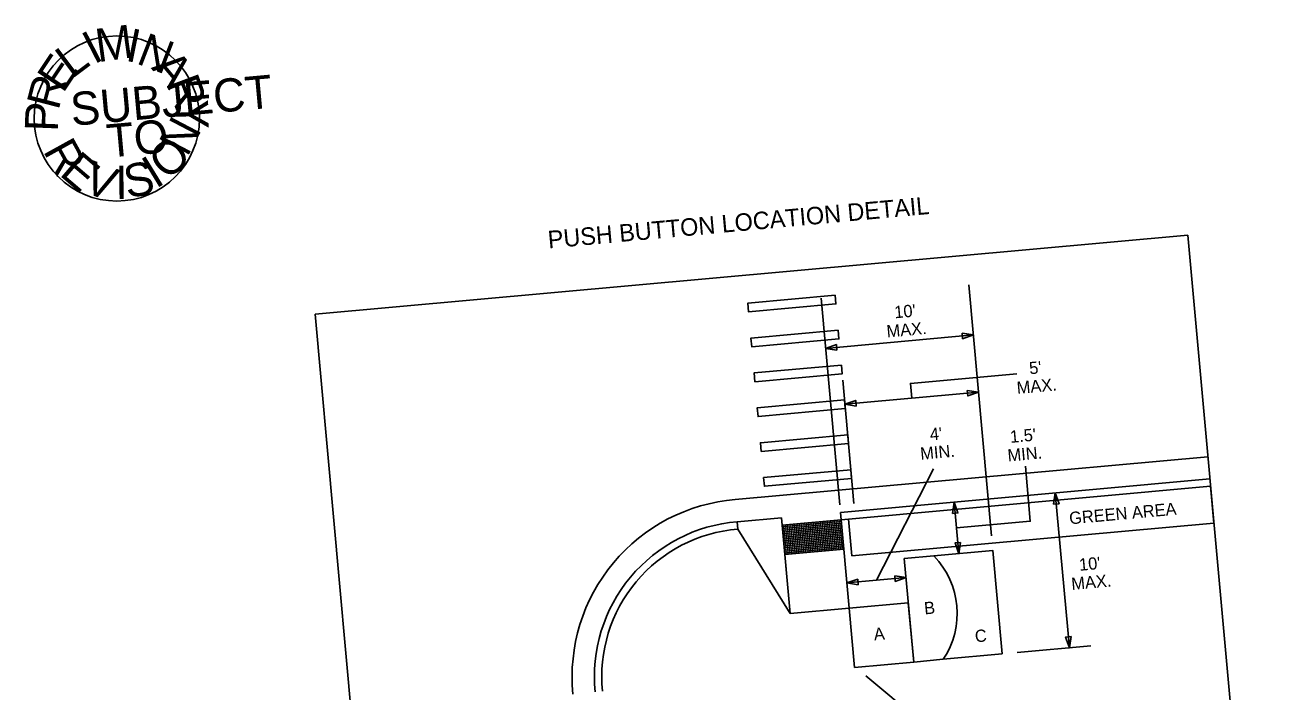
# Model space of a CAD drawing. Extents: x 1277218 to 1279252, y 196905 to 197529.
# Drawn here: x 1278236.5 to 1278669.3, y 197213 to 197445.9 of the extents above; entities that cross this region are included whole.
import ezdxf

# ---------------------------------------------------------------- set-up
doc = ezdxf.new("R2010")
doc.units = 0
doc.layers.add('C-ANNO-SYMB', color=7, linetype='Continuous')
doc.layers.add('C-TOPO-SURF-VOID', color=7, linetype='Continuous')

msp = doc.modelspace()

# ---------------------------------------------------------------- linework, layer by layer
at = {"layer": 'C-ANNO-SYMB'}
msp.add_circle((1278268.61, 197413.17), 28.85, dxfattribs=at)
at = {"layer": 'C-TOPO-SURF-VOID'}
for p, q in [((1278337.83, 197344.75), (1278642.58, 197372.36)), ((1278642.58, 197372.36), (1278669.26, 197077.94)), ((1278574.07, 197267.33), (1278566.13, 197355.03)), ((1278521.08, 197278.13), (1278514.54, 197350.36)), ((1278364.51, 197050.32), (1278337.83, 197344.75)), ((1278516.12, 197332.85), (1278567.71, 197337.52)), ((1278526, 197278.58), (1278522.09, 197321.73)), ((1278522.85, 197313.31), (1278569.52, 197317.54)), ((1278484.5, 197280.02), (1278649.59, 197294.98)), ((1278533.87, 197251.81), (1278553.76, 197290.79)), ((1278521.31, 197275.55), (1278650.29, 197287.24)), ((1278521.55, 197272.97), (1278650.52, 197284.66)), ((1278651.69, 197271.76), (1278650.52, 197284.66)), ((1278596.32, 197282.35), (1278601.23, 197228.18)), ((1278524.35, 197242.02), (1278521.31, 197275.55)), ((1278560.98, 197279.15), (1278562.61, 197261.09)), ((1278485.2, 197272.28), (1278500.68, 197273.68)), ((1278485.2, 197272.28), (1278485.44, 197269.7)), ((1278503.72, 197240.15), (1278500.68, 197273.68)), ((1278521.55, 197272.97), (1278500.91, 197271.1)), ((1278525.3, 197260.31), (1278524.13, 197273.21)), ((1278525.3, 197260.31), (1278651.69, 197271.76)), ((1278485.44, 197269.7), (1278503.72, 197240.15)), ((1278500.91, 197271.1), (1278503.72, 197240.15)), ((1278522.48, 197262.66), (1278501.85, 197260.79)), ((1278543.59, 197259.37), (1278553.9, 197260.3)), ((1278546.86, 197223.25), (1278543.59, 197259.37)), ((1278523.55, 197250.87), (1278544.19, 197252.74)), ((1278503.72, 197240.15), (1278524.35, 197242.02)), ((1278582.97, 197226.53), (1278608.77, 197228.86)), ((1278546.86, 197223.25), (1278557.18, 197224.19)), ((1278557.18, 197224.19), (1278577.81, 197226.06)), ((1278530.19, 197218.42), (1278550.08, 197201.84))]:
    msp.add_line(p, q, dxfattribs=at)
for points in [[(1278519.4, 197351.4), (1278519.68, 197348.36), (1278489.2, 197345.59), (1278488.93, 197348.64)], [(1278520.51, 197339.21), (1278520.78, 197336.17), (1278490.31, 197333.4), (1278490.03, 197336.45)], [(1278563.76, 197338.14), (1278567.71, 197337.52), (1278563.93, 197336.21)], [(1278520.08, 197332.23), (1278516.12, 197332.85), (1278519.9, 197334.17)], [(1278521.61, 197327.02), (1278521.89, 197323.98), (1278491.41, 197321.21), (1278491.14, 197324.26)], [(1278522.71, 197314.83), (1278522.99, 197311.79), (1278492.52, 197309.02), (1278492.24, 197312.07)], [(1278526.81, 197312.69), (1278522.85, 197313.31), (1278526.63, 197314.63)], [(1278565.57, 197318.16), (1278569.52, 197317.54), (1278565.74, 197316.22)], [(1278523.82, 197302.64), (1278524.1, 197299.6), (1278493.62, 197296.84), (1278493.34, 197299.88)], [(1278524.92, 197290.45), (1278525.2, 197287.41), (1278494.73, 197284.65), (1278494.45, 197287.69)], [(1278595.7, 197278.39), (1278596.32, 197282.35), (1278597.64, 197278.57)], [(1278560.36, 197275.19), (1278560.98, 197279.15), (1278562.29, 197275.37)], [(1278563.23, 197265.05), (1278562.61, 197261.09), (1278561.3, 197264.87)], [(1278527.51, 197250.25), (1278523.55, 197250.87), (1278527.33, 197252.19)], [(1278540.23, 197253.36), (1278544.19, 197252.74), (1278540.41, 197251.42)], [(1278524.35, 197242.02), (1278526.22, 197221.38), (1278546.86, 197223.25), (1278544.99, 197243.89)], [(1278601.84, 197232.14), (1278601.23, 197228.18), (1278599.91, 197231.96)]]:
    msp.add_lwpolyline(points, close=True, dxfattribs=at)
for points in [[(1278546.19, 197315.42), (1278545.72, 197320.58), (1278582.84, 197323.95)], [(1278561.8, 197270.12), (1278587.59, 197272.46), (1278585.85, 197291.66)], [(1278577.81, 197226.06), (1278574.54, 197262.17), (1278553.9, 197260.3)]]:
    msp.add_lwpolyline(points, dxfattribs=at)
for centre in [(1278507.02, 197271.04), (1278507.63, 197271.1), (1278508.24, 197271.15), (1278508.85, 197271.21), (1278509.46, 197271.26), (1278510.07, 197271.32), (1278510.68, 197271.37), (1278511.29, 197271.43), (1278511.9, 197271.49), (1278512.5, 197271.54), (1278513.11, 197271.6), (1278513.72, 197271.65), (1278513.78, 197271.04), (1278514.33, 197271.71), (1278514.39, 197271.1), (1278514.94, 197271.76), (1278515, 197271.15), (1278515.55, 197271.82), (1278515.61, 197271.21), (1278516.16, 197271.87), (1278516.22, 197271.26), (1278516.77, 197271.93), (1278516.83, 197271.32), (1278517.38, 197271.98), (1278517.44, 197271.37), (1278517.99, 197272.04), (1278518.05, 197271.43), (1278518.6, 197272.09), (1278518.65, 197271.48), (1278519.21, 197272.15), (1278519.26, 197271.54), (1278519.82, 197272.2), (1278519.87, 197271.59), (1278520.43, 197272.26), (1278520.48, 197271.65), (1278520.54, 197271.04), (1278521.04, 197272.31), (1278521.09, 197271.7), (1278521.15, 197271.09), (1278501.53, 197270.55), (1278501.59, 197269.94), (1278501.64, 197269.33), (1278501.7, 197268.72), (1278501.75, 197268.11), (1278501.81, 197267.5), (1278501.87, 197266.89), (1278502.14, 197270.6), (1278502.2, 197269.99), (1278502.25, 197269.38), (1278502.31, 197268.77), (1278502.36, 197268.16), (1278502.42, 197267.55), (1278502.47, 197266.94), (1278502.75, 197270.66), (1278502.81, 197270.05), (1278502.86, 197269.44), (1278502.92, 197268.83), (1278502.97, 197268.22), (1278503.03, 197267.61), (1278503.08, 197267), (1278503.36, 197270.71), (1278503.42, 197270.1), (1278503.47, 197269.49), (1278503.53, 197268.88), (1278503.58, 197268.27), (1278503.64, 197267.66), (1278503.69, 197267.05), (1278503.97, 197270.77), (1278504.03, 197270.16), (1278504.08, 197269.55), (1278504.14, 197268.94), (1278504.19, 197268.33), (1278504.25, 197267.72), (1278504.3, 197267.11), (1278504.58, 197270.82), (1278504.64, 197270.21), (1278504.69, 197269.6), (1278504.75, 197268.99), (1278504.8, 197268.38), (1278504.86, 197267.77), (1278504.91, 197267.17), (1278505.19, 197270.88), (1278505.25, 197270.27), (1278505.3, 197269.66), (1278505.36, 197269.05), (1278505.41, 197268.44), (1278505.47, 197267.83), (1278505.52, 197267.22), (1278505.8, 197270.93), (1278505.86, 197270.32), (1278505.91, 197269.71), (1278505.97, 197269.1), (1278506.02, 197268.49), (1278506.08, 197267.89), (1278506.13, 197267.28), (1278506.41, 197270.99), (1278506.46, 197270.38), (1278506.52, 197269.77), (1278506.58, 197269.16), (1278506.63, 197268.55), (1278506.69, 197267.94), (1278506.74, 197267.33), (1278506.8, 197266.72), (1278507.07, 197270.43), (1278507.13, 197269.82), (1278507.18, 197269.21), (1278507.24, 197268.61), (1278507.3, 197268), (1278507.35, 197267.39), (1278507.41, 197266.78), (1278507.68, 197270.49), (1278507.74, 197269.88), (1278507.79, 197269.27), (1278507.85, 197268.66), (1278507.9, 197268.05), (1278507.96, 197267.44), (1278508.02, 197266.83), (1278508.29, 197270.54), (1278508.35, 197269.93), (1278508.4, 197269.33), (1278508.46, 197268.72), (1278508.51, 197268.11), (1278508.57, 197267.5), (1278508.62, 197266.89), (1278508.9, 197270.6), (1278508.96, 197269.99), (1278509.01, 197269.38), (1278509.07, 197268.77), (1278509.12, 197268.16), (1278509.18, 197267.55), (1278509.23, 197266.94), (1278509.51, 197270.65), (1278509.57, 197270.05), (1278509.62, 197269.44), (1278509.68, 197268.83), (1278509.73, 197268.22), (1278509.79, 197267.61), (1278509.84, 197267), (1278510.12, 197270.71), (1278510.18, 197270.1), (1278510.23, 197269.49), (1278510.29, 197268.88), (1278510.34, 197268.27), (1278510.4, 197267.66), (1278510.45, 197267.05), (1278510.73, 197270.77), (1278510.79, 197270.16), (1278510.84, 197269.55), (1278510.9, 197268.94), (1278510.95, 197268.33), (1278511.01, 197267.72), (1278511.06, 197267.11), (1278511.34, 197270.82), (1278511.4, 197270.21), (1278511.45, 197269.6), (1278511.51, 197268.99), (1278511.56, 197268.38), (1278511.62, 197267.77), (1278511.67, 197267.16), (1278511.95, 197270.88), (1278512.01, 197270.27), (1278512.06, 197269.66), (1278512.12, 197269.05), (1278512.17, 197268.44), (1278512.23, 197267.83), (1278512.28, 197267.22), (1278512.56, 197270.93), (1278512.62, 197270.32), (1278512.67, 197269.71), (1278512.73, 197269.1), (1278512.78, 197268.49), (1278512.84, 197267.88), (1278512.89, 197267.27), (1278513.17, 197270.99), (1278513.22, 197270.38), (1278513.28, 197269.77), (1278513.34, 197269.16), (1278513.39, 197268.55), (1278513.45, 197267.94), (1278513.5, 197267.33), (1278513.56, 197266.72), (1278513.83, 197270.43), (1278513.89, 197269.82), (1278513.94, 197269.21), (1278514, 197268.6), (1278514.05, 197267.99), (1278514.11, 197267.38), (1278514.17, 197266.77), (1278514.44, 197270.49), (1278514.5, 197269.88), (1278514.55, 197269.27), (1278514.61, 197268.66), (1278514.66, 197268.05), (1278514.72, 197267.44), (1278514.77, 197266.83), (1278515.05, 197270.54), (1278515.11, 197269.93), (1278515.16, 197269.32), (1278515.22, 197268.71), (1278515.27, 197268.1), (1278515.33, 197267.49), (1278515.38, 197266.89), (1278515.66, 197270.6), (1278515.72, 197269.99), (1278515.77, 197269.38), (1278515.83, 197268.77), (1278515.88, 197268.16), (1278515.94, 197267.55), (1278515.99, 197266.94), (1278516.27, 197270.65), (1278516.33, 197270.04), (1278516.38, 197269.43), (1278516.44, 197268.82), (1278516.49, 197268.21), (1278516.55, 197267.61), (1278516.6, 197267), (1278516.88, 197270.71), (1278516.94, 197270.1), (1278516.99, 197269.49), (1278517.05, 197268.88), (1278517.1, 197268.27), (1278517.16, 197267.66), (1278517.21, 197267.05), (1278517.49, 197270.76), (1278517.55, 197270.15), (1278517.6, 197269.54), (1278517.66, 197268.93), (1278517.71, 197268.33), (1278517.77, 197267.72), (1278517.82, 197267.11), (1278518.1, 197270.82), (1278518.16, 197270.21), (1278518.21, 197269.6), (1278518.27, 197268.99), (1278518.32, 197268.38), (1278518.38, 197267.77), (1278518.43, 197267.16), (1278518.71, 197270.87), (1278518.77, 197270.26), (1278518.82, 197269.65), (1278518.88, 197269.05), (1278518.93, 197268.44), (1278518.99, 197267.83), (1278519.04, 197267.22), (1278519.32, 197270.93), (1278519.37, 197270.32), (1278519.43, 197269.71), (1278519.49, 197269.1), (1278519.54, 197268.49), (1278519.6, 197267.88), (1278519.65, 197267.27), (1278519.93, 197270.98), (1278519.98, 197270.37), (1278520.04, 197269.77), (1278520.09, 197269.16), (1278520.15, 197268.55), (1278520.21, 197267.94), (1278520.26, 197267.33), (1278520.32, 197266.72), (1278520.59, 197270.43), (1278520.65, 197269.82), (1278520.7, 197269.21), (1278520.76, 197268.6), (1278520.81, 197267.99), (1278520.87, 197267.38), (1278520.93, 197266.77), (1278521.2, 197270.49), (1278521.26, 197269.88), (1278521.31, 197269.27), (1278521.37, 197268.66), (1278521.42, 197268.05), (1278521.48, 197267.44), (1278521.53, 197266.83), (1278501.92, 197266.28), (1278501.98, 197265.67), (1278502.03, 197265.06), (1278502.09, 197264.45), (1278502.14, 197263.84), (1278502.2, 197263.23), (1278502.25, 197262.62), (1278502.53, 197266.33), (1278502.59, 197265.73), (1278502.64, 197265.12), (1278502.7, 197264.51), (1278502.75, 197263.9), (1278502.81, 197263.29), (1278502.86, 197262.68), (1278503.14, 197266.39), (1278503.19, 197265.78), (1278503.25, 197265.17), (1278503.3, 197264.56), (1278503.36, 197263.95), (1278503.42, 197263.34), (1278503.47, 197262.73), (1278503.75, 197266.45), (1278503.8, 197265.84), (1278503.86, 197265.23), (1278503.91, 197264.62), (1278503.97, 197264.01), (1278504.02, 197263.4), (1278504.08, 197262.79), (1278504.36, 197266.5), (1278504.41, 197265.89), (1278504.47, 197265.28), (1278504.52, 197264.67), (1278504.58, 197264.06), (1278504.63, 197263.45), (1278504.69, 197262.84), (1278504.97, 197266.56), (1278505.02, 197265.95), (1278505.08, 197265.34), (1278505.13, 197264.73), (1278505.19, 197264.12), (1278505.24, 197263.51), (1278505.3, 197262.9), (1278505.58, 197266.61), (1278505.63, 197266), (1278505.69, 197265.39), (1278505.74, 197264.78), (1278505.8, 197264.17), (1278505.85, 197263.56), (1278505.91, 197262.95), (1278506.19, 197266.67), (1278506.24, 197266.06), (1278506.3, 197265.45), (1278506.35, 197264.84), (1278506.41, 197264.23), (1278506.46, 197263.62), (1278506.52, 197263.01), (1278506.57, 197262.4), (1278506.85, 197266.11), (1278506.91, 197265.5), (1278506.96, 197264.89), (1278507.02, 197264.28), (1278507.07, 197263.67), (1278507.13, 197263.06), (1278507.18, 197262.46), (1278507.46, 197266.17), (1278507.52, 197265.56), (1278507.57, 197264.95), (1278507.63, 197264.34), (1278507.68, 197263.73), (1278507.74, 197263.12), (1278507.79, 197262.51), (1278508.07, 197266.22), (1278508.13, 197265.61), (1278508.18, 197265), (1278508.24, 197264.39), (1278508.29, 197263.78), (1278508.35, 197263.18), (1278508.4, 197262.57), (1278508.68, 197266.28), (1278508.74, 197265.67), (1278508.79, 197265.06), (1278508.85, 197264.45), (1278508.9, 197263.84), (1278508.96, 197263.23), (1278509.01, 197262.62), (1278509.29, 197266.33), (1278509.34, 197265.72), (1278509.4, 197265.11), (1278509.46, 197264.5), (1278509.51, 197263.9), (1278509.57, 197263.29), (1278509.62, 197262.68), (1278509.9, 197266.39), (1278509.95, 197265.78), (1278510.01, 197265.17), (1278510.06, 197264.56), (1278510.12, 197263.95), (1278510.18, 197263.34), (1278510.23, 197262.73), (1278510.51, 197266.44), (1278510.56, 197265.83), (1278510.62, 197265.22), (1278510.67, 197264.61), (1278510.73, 197264.01), (1278510.78, 197263.4), (1278510.84, 197262.79), (1278511.12, 197266.5), (1278511.17, 197265.89), (1278511.23, 197265.28), (1278511.28, 197264.67), (1278511.34, 197264.06), (1278511.39, 197263.45), (1278511.45, 197262.84), (1278511.73, 197266.55), (1278511.78, 197265.94), (1278511.84, 197265.33), (1278511.89, 197264.73), (1278511.95, 197264.12), (1278512, 197263.51), (1278512.06, 197262.9), (1278512.34, 197266.61), (1278512.39, 197266), (1278512.45, 197265.39), (1278512.5, 197264.78), (1278512.56, 197264.17), (1278512.61, 197263.56), (1278512.67, 197262.95), (1278512.95, 197266.66), (1278513, 197266.05), (1278513.06, 197265.45), (1278513.11, 197264.84), (1278513.17, 197264.23), (1278513.22, 197263.62), (1278513.28, 197263.01), (1278513.33, 197262.4), (1278513.61, 197266.11), (1278513.67, 197265.5), (1278513.72, 197264.89), (1278513.78, 197264.28), (1278513.83, 197263.67), (1278513.89, 197263.06), (1278513.94, 197262.45), (1278514.22, 197266.17), (1278514.28, 197265.56), (1278514.33, 197264.95), (1278514.39, 197264.34), (1278514.44, 197263.73), (1278514.5, 197263.12), (1278514.55, 197262.51), (1278514.83, 197266.22), (1278514.89, 197265.61), (1278514.94, 197265), (1278515, 197264.39), (1278515.05, 197263.78), (1278515.11, 197263.17), (1278515.16, 197262.56), (1278515.44, 197266.28), (1278515.49, 197265.67), (1278515.55, 197265.06), (1278515.61, 197264.45), (1278515.66, 197263.84), (1278515.72, 197263.23), (1278515.77, 197262.62), (1278516.05, 197266.33), (1278516.1, 197265.72), (1278516.16, 197265.11), (1278516.21, 197264.5), (1278516.27, 197263.89), (1278516.33, 197263.28), (1278516.38, 197262.67), (1278516.66, 197266.39), (1278516.71, 197265.78), (1278516.77, 197265.17), (1278516.82, 197264.56), (1278516.88, 197263.95), (1278516.93, 197263.34), (1278516.99, 197262.73), (1278517.27, 197266.44), (1278517.32, 197265.83), (1278517.38, 197265.22), (1278517.43, 197264.61), (1278517.49, 197264), (1278517.54, 197263.39), (1278517.6, 197262.78), (1278517.88, 197266.5), (1278517.93, 197265.89), (1278517.99, 197265.28), (1278518.04, 197264.67), (1278518.1, 197264.06), (1278518.15, 197263.45), (1278518.21, 197262.84), (1278518.49, 197266.55), (1278518.54, 197265.94), (1278518.6, 197265.33), (1278518.65, 197264.72), (1278518.71, 197264.11), (1278518.76, 197263.5), (1278518.82, 197262.89), (1278519.1, 197266.61), (1278519.15, 197266), (1278519.21, 197265.39), (1278519.26, 197264.78), (1278519.32, 197264.17), (1278519.37, 197263.56), (1278519.43, 197262.95), (1278519.71, 197266.66), (1278519.76, 197266.05), (1278519.82, 197265.44), (1278519.87, 197264.83), (1278519.93, 197264.22), (1278519.98, 197263.61), (1278520.04, 197263.01), (1278520.37, 197266.11), (1278520.43, 197265.5), (1278520.48, 197264.89), (1278520.54, 197264.28), (1278520.59, 197263.67), (1278520.65, 197263.06), (1278520.98, 197266.16), (1278521.04, 197265.55), (1278521.09, 197264.94), (1278521.15, 197264.33), (1278521.2, 197263.73), (1278521.26, 197263.12), (1278521.59, 197266.22), (1278521.65, 197265.61), (1278521.7, 197265), (1278521.76, 197264.39), (1278521.81, 197263.78), (1278521.87, 197263.17), (1278502.31, 197262.01), (1278502.36, 197261.4), (1278502.92, 197262.07), (1278502.97, 197261.46), (1278503.53, 197262.12), (1278503.58, 197261.51), (1278504.14, 197262.18), (1278504.19, 197261.57), (1278504.74, 197262.23), (1278504.8, 197261.62), (1278505.35, 197262.29), (1278505.41, 197261.68), (1278505.96, 197262.34), (1278506.02, 197261.74), (1278506.63, 197261.79), (1278507.24, 197261.85), (1278507.85, 197261.9), (1278508.46, 197261.96), (1278509.07, 197262.01), (1278509.68, 197262.07), (1278510.29, 197262.12), (1278510.9, 197262.18), (1278511.5, 197262.23), (1278512.11, 197262.29), (1278512.72, 197262.34)]:
    msp.add_circle(centre, 0.115, dxfattribs=at)
for centre, radius, start, end in [((1278489.74, 197218.08), 62.16, 94.7692, 185.5865), ((1278489.74, 197218.08), 54.39, 94.7692, 185.5865), ((1278489.74, 197218.08), 51.8, 94.7692, 185.5865), ((1278533.29, 197240.23), 28.77, 326.1201, 44.2357)]:
    msp.add_arc(centre, radius, start, end, dxfattribs=at)

# ---------------------------------------------------------------- texts
at = {"layer": 'C-ANNO-SYMB'}
for s, height, rotation, p in [('M', 11.6, 7.8722, (1278261.98, 197432.83)), ('I', 11.6, 348.556, (1278271.29, 197433.43)), ('I', 11.6, 27.1884, (1278260.61, 197431.97)), ('N', 11.6, 338.8978, (1278275.03, 197432.53)), ('E', 11.6, 56.1628, (1278249.81, 197421.73)), ('L', 11.6, 36.8465, (1278252.94, 197426.9)), ('A', 11.6, 309.9235, (1278280.4, 197430.83)), ('R', 11.6, 75.479, (1278248.23, 197415.77)), ('SUBJECT', 11.603, 5.1779, (1278252.95, 197410.59)), ('R', 11.6, 290.6072, (1278285.68, 197425.68)), ('P', 11.6, 87.7868, (1278248.02, 197408.43)), ('Y', 11.6, 271.291, (1278288.87, 197419.67)), ('TO', 11.603, 5.1779, (1278265.61, 197399.49)), ('N', 11.6, 62.3156, (1278293.22, 197399.47)), ('R', 11.6, 298.9418, (1278242.68, 197401.89)), ('O', 11.6, 41.7533, (1278286.31, 197391.24)), ('E', 11.6, 319.5041, (1278248.22, 197393.55)), ('V', 11.6, 340.0664, (1278256.33, 197387.67)), ('I', 11.6, 0.6287, (1278268.13, 197385.02)), ('S', 11.6, 10.9099, (1278272.29, 197385.22)), ('I', 11.6, 31.4722, (1278282.22, 197388.48))]:
    msp.add_text(s, height=height, rotation=rotation, dxfattribs=at).set_placement(p)
at = {"layer": 'C-TOPO-SURF-VOID'}
for s, height, p in [('PUSH BUTTON LOCATION DETAIL', 6.1199, (1278419.39, 197367.75)), ("10'", 4.284, (1278540.29, 197343.33)), ('MAX.', 4.284, (1278537.58, 197336.64)), ("5'", 4.284, (1278587.39, 197323.77)), ('MAX.', 4.284, (1278583.03, 197316.92)), ("4'", 4.284, (1278552.7, 197300.65)), ("1.5'", 4.284, (1278580.7, 197299.81)), ('MIN.', 4.284, (1278549.34, 197293.9)), ('MIN.', 4.284, (1278579.82, 197293.28)), ('GREEN AREA', 4.284, (1278601.36, 197271.34)), ("10'", 4.284, (1278604.8, 197255.11)), ('MAX.', 4.284, (1278602.09, 197248.41)), ('B', 4.28, (1278550.7, 197239.87)), ('A', 4.28, (1278533.11, 197230.79)), ('C', 4.28, (1278568.42, 197230.1))]:
    msp.add_text(s, height=height, rotation=5.1779, dxfattribs=at).set_placement(p)

doc.saveas('drawing.dxf')
